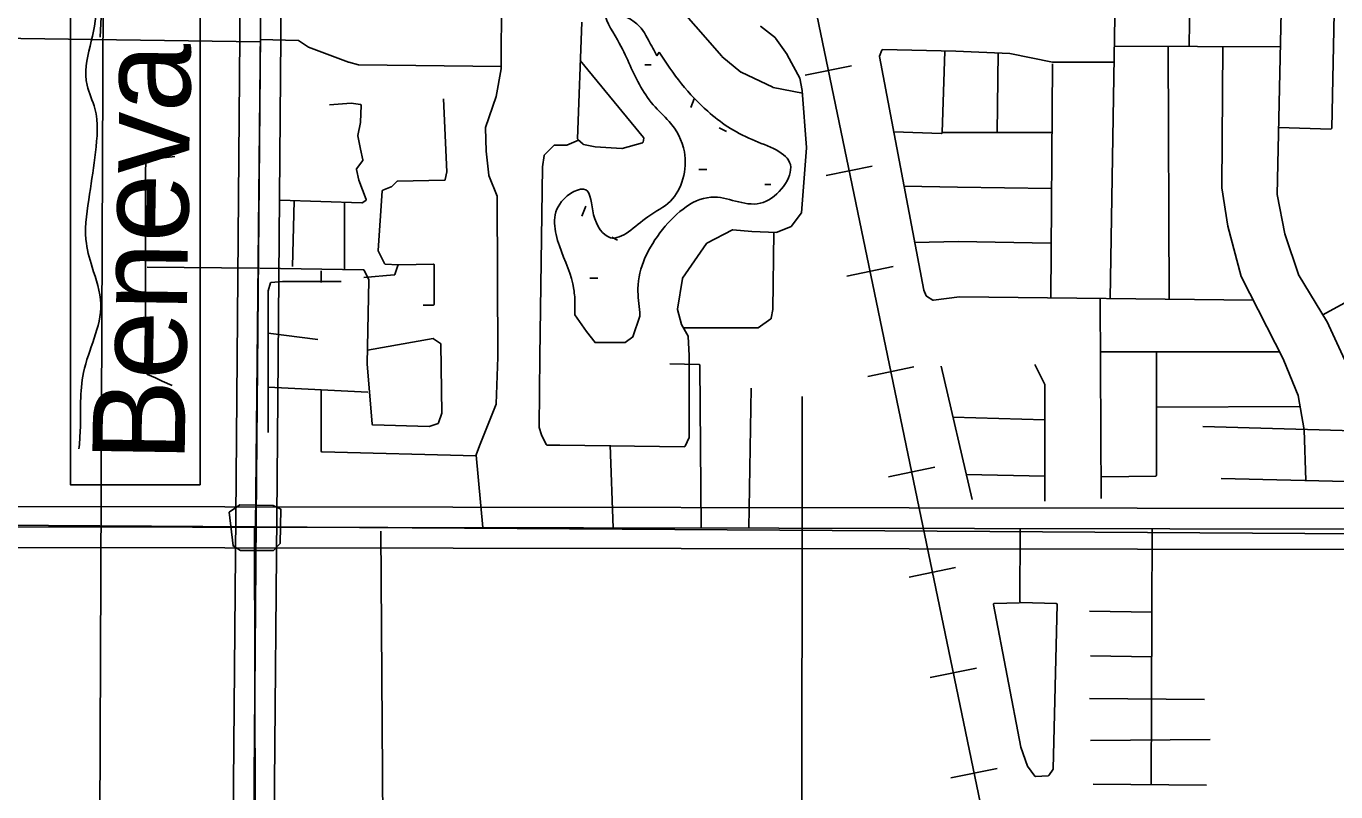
# Model space of a CAD drawing. Extents: x 408847 to 817539, y 923858 to 1151780.
# Drawn here: x 493482 to 499864, y 1076805 to 1080539 of the extents above; entities that cross this region are included whole.
import ezdxf

# ---------------------------------------------------------------- set-up
doc = ezdxf.new("R2010")
doc.units = 0
for name, color, linetype in [('County Roads Related Text', 7, 'Continuous'), ('County Route Divided Highway Outline and Fill', 7, 'Continuous'), ('County Routes Highway Center Lines', 7, 'Continuous'), ('Lakes and Ponds', 7, 'Continuous'), ('Level 12', 7, 'Continuous'), ('Level 7', 7, 'Continuous'), ('Level 8', 7, 'Continuous'), ('Local Roads Improved', 7, 'Continuous'), ('Local Roads Paved', 7, 'Continuous'), ('Masks for Road Features', 7, 'Continuous'), ('Masks for Text', 7, 'Continuous'), ('Narrow River Creek and Branch and Slough', 7, 'Continuous'), ('Quad Borders', 7, 'Continuous'), ('Railroads', 7, 'Continuous'), ('Section Lines', 7, 'Continuous'), ('Township  and Range lines', 7, 'Continuous')]:
    doc.layers.add(name, color=color, linetype=linetype)

msp = doc.modelspace()

# ---------------------------------------------------------------- linework, layer by layer
at = {"layer": 'County Route Divided Highway Outline and Fill'}
for p, q in [((494568, 1085769.8), (494505.3, 1078336)), ((494668, 1085769), (494605.3, 1078335.2)), ((494768, 1085768.2), (494705.3, 1078334.3)), ((494705.3, 1078334.3), (494768, 1085768.2)), ((494505.3, 1078336), (494302.9, 1054340.5)), ((494605.3, 1078335.2), (494402.6, 1054313.9)), ((494705.3, 1078334.3), (494502.5, 1054302.3)), ((494502.5, 1054302.3), (494705.3, 1078334.3))]:
    msp.add_line(p, q, dxfattribs=at)
at = {"layer": 'County Routes Highway Center Lines'}
for p, q in [((494605.3, 1078335.2), (494668, 1085769)), ((494402.6, 1054313.9), (494605.3, 1078335.2))]:
    msp.add_line(p, q, dxfattribs=at)
at = {"layer": 'Lakes and Ponds'}
msp.add_line((496567.6, 1080412.3), (496555.6, 1080394.3), dxfattribs=at)
msp.add_lwpolyline([(496155.4, 1079219.8), (496155.3, 1079131.6), (496212.2, 1079050.8), (496254.4, 1078995.7), (496401.2, 1078995.7), (496437.9, 1079023.2), (496472.7, 1079124.2), (496473.5, 1079143.5)], dxfattribs=at)
for points in [[(496555.6, 1080394.3), (496515.6, 1080470.4), (496445.5, 1080560.5), (496309.4, 1080602.5), (496363.4, 1080472.4), (496419.5, 1080360.3), (496537.3, 1080156.1), (496615.7, 1080074), (496689.8, 1079925.8), (496621.7, 1079685.6), (496511.6, 1079609.5), (496329.4, 1079507.4), (496247.3, 1079619.5), (496209.3, 1079741.6), (496091.2, 1079683.6), (496081.2, 1079467.4), (496151.2, 1079255.2), (496155.4, 1079219.8)], [(496473.5, 1079143.5), (496463.5, 1079259.2), (496583.7, 1079547.4), (496835.9, 1079705.6), (497074.2, 1079679.6), (497206.3, 1079863.8), (497020.1, 1079985.9), (496803.9, 1080124), (496675.8, 1080258.2), (496567.6, 1080412.3)]]:
    msp.add_spline(points, degree=3, dxfattribs=at)
at = {"layer": 'Level 12'}
for p, q in [((496497.8, 1080351.1), (496527.7, 1080351.1)), ((496859.7, 1080044.1), (496894.5, 1080025.4)), ((496760.2, 1079840.8), (496798.5, 1079840.8)), ((497081.2, 1079767.8), (497111, 1079767.8)), ((496190.9, 1079612.6), (496209.6, 1079661.1)), ((496229.9, 1079310.5), (496268.1, 1079310.5))]:
    msp.add_line(p, q, dxfattribs=at)
for points in [[(496721.3, 1080142.9), (496737.2, 1080184.4)], [(496336.8, 1079509.8), (496364.2, 1079495)]]:
    msp.add_lwpolyline(points, dxfattribs=at)
msp.add_spline([(493827.7, 1080893.9), (493803.6, 1080761.7), (493821.6, 1080635.6), (493778.8, 1080251.5), (493817.6, 1080137), (493819.6, 1079924.8), (493791.6, 1079720.6), (493773.6, 1079498.3), (493803.6, 1079364.2), (493845.7, 1079184), (493761.6, 1078849.6), (493745.6, 1078565.3), (493739.6, 1078477.2)], degree=3, dxfattribs=at)
at = {"layer": 'Level 7'}
for p, q in [((483896.7, 1078211.6), (513104.2, 1078166.3)), ((513104.1, 1078066.3), (483896.5, 1078111.6)), ((513103.9, 1077966.3), (483896.4, 1078011.6))]:
    msp.add_line(p, q, dxfattribs=at)
at = {"layer": 'Level 8'}
msp.add_line((494668, 1085769), (494605.3, 1078335.2), dxfattribs=at)
at = {"layer": 'Local Roads Improved'}
for p, q in [((496189.8, 1080558.8), (496169.5, 1079989.3)), ((496491, 1079997), (496181.6, 1080371.6)), ((496488.5, 1079973.6), (496491.9, 1079993.8)), ((496170.8, 1079986.1), (496197.2, 1079963.5)), ((496199, 1079962.7), (496254.9, 1079950.7)), ((496255.5, 1079950.6), (496385.3, 1079942.5)), ((496386.6, 1079942.6), (496485.6, 1079970.4))]:
    msp.add_line(p, q, dxfattribs=at)
for centre, start, end in [((496173.5, 1079989.2), 177.95554, 229.38551), ((496487.9, 1079994.4), 350.54201, 39.54656), ((496199.8, 1079966.6), 229.38551, 257.89977), ((496255.7, 1079954.6), 257.89977, 266.422), ((496385.5, 1079946.5), 266.422, 285.64918), ((496484.6, 1079974.2), 285.64918, 350.54201)]:
    msp.add_arc(centre, 4, start, end, dxfattribs=at)
at = {"layer": 'Local Roads Paved'}
for p, q in [((495801.7, 1081402.7), (495797.6, 1080331.1)), ((496190.9, 1081175.7), (496871.9, 1080392.3)), ((499158.1, 1081018.5), (499150, 1080440.3)), ((498794.5, 1081006.2), (498765.6, 1079211.4)), ((498765.6, 1079211.4), (498794.5, 1081006.2)), ((499607.4, 1081007.4), (499579, 1079719)), ((493859.5, 1080850.5), (493843, 1080486.1)), ((499844.6, 1080041.5), (499860.9, 1080863.1)), ((497133.2, 1080482.4), (497060.1, 1080539.2)), ((493103.5, 1080483.6), (494623.2, 1080463)), ((494623.3, 1080474.9), (494807.7, 1080469.8)), ((494809.8, 1080469.1), (494857.5, 1080437.3)), ((494858.3, 1080436.9), (495053.8, 1080363.5)), ((497190.7, 1080400.5), (497134, 1080481.5)), ((498785.4, 1080442.2), (499594.8, 1080438)), ((499047.8, 1080440.8), (499051.9, 1079208.1)), ((499313.4, 1080439.5), (499309.3, 1079751.6)), ((496872.4, 1080391.9), (496965.7, 1080314.7)), ((497251.8, 1080286.3), (497190.9, 1080400)), ((497640.5, 1080391), (497856.7, 1079252)), ((497651.5, 1080422.1), (497640.7, 1080393.1)), ((498012.1, 1080416.6), (497655.4, 1080424.7)), ((497946.8, 1080020), (497959.4, 1080417.8)), ((497959.4, 1080417.8), (497946.8, 1080020)), ((498275.3, 1080405.3), (498012.1, 1080416.6)), ((498214.1, 1080021), (498218.4, 1080409.4)), ((498483.6, 1080364.5), (498275.9, 1080405.3)), ((495054.2, 1080363.4), (495102.5, 1080351.3)), ((495103.5, 1080351.2), (495797.6, 1080343)), ((495797.5, 1080330.4), (495773.1, 1080196.2)), ((496966.6, 1080314.2), (497120.9, 1080241.1)), ((498475.7, 1079214.7), (498484, 1080356.3)), ((498784.2, 1080364.5), (498484.4, 1080364.5)), ((497264.3, 1080224.7), (497252.2, 1080285.2)), ((495532, 1079829.4), (495515.7, 1080184.6)), ((495773, 1080195.6), (495720.2, 1080045.3)), ((497121.9, 1080240.7), (497265.2, 1080213)), ((497284.8, 1079946.8), (497264.4, 1080224.2)), ((495065.7, 1080164.1), (494960, 1080156)), ((495111.8, 1080156.5), (495066.7, 1080164.1)), ((495111.2, 1080070.4), (495115.1, 1080152.4)), ((495099.1, 1080005.4), (495111.1, 1080069.8)), ((495111.2, 1079939.4), (495099.1, 1080004)), ((495720, 1080043.9), (495724, 1079930.3)), ((497710.1, 1080024.5), (497942.7, 1080016.2)), ((497942.7, 1080016.2), (497710.1, 1080024.5)), ((497946.9, 1080021), (498481.5, 1080021)), ((499587.1, 1080045.6), (499840.5, 1080037.6)), ((495123, 1079887.9), (495111.2, 1079939.2)), ((495724.1, 1079930), (495736.2, 1079812.2)), ((496053.8, 1079957.6), (496006.9, 1079910.7)), ((496053.8, 1079957.6), (496006.9, 1079910.7)), ((496115.5, 1079958.8), (496056.6, 1079958.8)), ((496115.5, 1079958.8), (496056.6, 1079958.8)), ((496174.5, 1079983), (496117, 1079959.1)), ((496174.5, 1079983), (496117, 1079959.1)), ((497260.4, 1079628.8), (497284.8, 1079946.2)), ((494067.4, 1079883.6), (494063.6, 1079842)), ((494206.6, 1079903.2), (494070.9, 1079887.2)), ((495091.8, 1079842.7), (495122.4, 1079884.7)), ((496005.8, 1079908.4), (495997.8, 1079852.8)), ((496005.8, 1079908.4), (495997.8, 1079852.8)), ((494063.6, 1079841.7), (494063.6, 1078901.9)), ((495102.9, 1079788.3), (495091.2, 1079839.4)), ((495524.5, 1079791.2), (495531.9, 1079828.5)), ((495736.5, 1079811.1), (495776.9, 1079710.1)), ((495997.8, 1079852.2), (495985.5, 1078928.7)), ((495997.8, 1079852.2), (495985.5, 1078928.7)), ((495138.6, 1079693.1), (495103.1, 1079787.8)), ((495197, 1079445.8), (495217.2, 1079736.4)), ((495219.8, 1079739.9), (495261.5, 1079755.1)), ((495263, 1079756), (495289.8, 1079782.8)), ((495292.6, 1079784), (495520.6, 1079788)), ((497760.5, 1079758.7), (498020.2, 1079754.4)), ((498020.2, 1079754.4), (498479.6, 1079747)), ((499309.3, 1079751), (499337.9, 1079563.5)), ((494718.9, 1079690), (495118.2, 1079677.7)), ((494780.2, 1079367), (494788.7, 1079687.8)), ((495033.5, 1079354.8), (495033.2, 1079680.3)), ((495120.4, 1079678.3), (495136.9, 1079688.2)), ((495777.2, 1079708.7), (495781.2, 1078924.6)), ((499579, 1079718.2), (499615.7, 1079526.8)), ((497211.9, 1079563.2), (497259.6, 1079626.8)), ((496799.5, 1079481), (496924.2, 1079545.4)), ((496926.4, 1079545.8), (497019.1, 1079537.8)), ((497142.6, 1079534), (497210.2, 1079561.9)), ((499337.9, 1079563.1), (499403.2, 1079318.4)), ((496680.6, 1079309.6), (496798, 1079479.7)), ((497019.3, 1079537.8), (497140.9, 1079533.7)), ((497121.4, 1079157.9), (497125.7, 1079534.2)), ((497812.6, 1079484.3), (498024.3, 1079488.7)), ((498024.3, 1079488.7), (498475.8, 1079481.5)), ((499615.8, 1079526.2), (499685, 1079322.5)), ((495228.6, 1079381.4), (495197.5, 1079443.7)), ((494071.8, 1079363.6), (494613.9, 1079359)), ((494620.9, 1079358.9), (495125.1, 1079350.7)), ((495295, 1079375.2), (495232, 1079379.2)), ((495279.5, 1079328.7), (495294.1, 1079372.5)), ((495297.8, 1079375.3), (495466.6, 1079379.2)), ((495470.7, 1079375.2), (495470.7, 1079183)), ((499801.8, 1079131.2), (500263.3, 1079387.3)), ((494661.9, 1079249.1), (494673.2, 1079286.7)), ((494676.7, 1079289.6), (494731.1, 1079293.4)), ((494731.3, 1079293.5), (495017.2, 1079293.5)), ((494919.1, 1079289.4), (494919.1, 1079346.6)), ((495127.5, 1079313.9), (495276.1, 1079325.9)), ((495128.6, 1079348.5), (495151.6, 1079302.5)), ((495152, 1079300.6), (495143.9, 1078893.1)), ((496655.7, 1079158.5), (496680, 1079308)), ((499403.5, 1079317.6), (499611.6, 1078909.4)), ((499685.4, 1079321.7), (499819.9, 1079101.6)), ((494661.7, 1078557.7), (494661.7, 1079247.9)), ((497857, 1079251.2), (497868.6, 1079224.2)), ((497870.1, 1079222.3), (497900.5, 1079203.3)), ((495466.7, 1079179), (495417.6, 1079179)), ((497903.2, 1079202.8), (498030.4, 1079219.9)), ((498030.4, 1079219.9), (499461.7, 1079203.3)), ((498716.9, 1079211.7), (498720.9, 1078234.8)), ((496675.9, 1079084.5), (496655.8, 1079156.8)), ((497048.9, 1079068.4), (497111.8, 1079111.7)), ((497113.5, 1079114.3), (497121.3, 1079157.3)), ((499820.1, 1079101.2), (499917.9, 1078889.1)), ((494661.7, 1079042.1), (494902.8, 1079011.4)), ((496708.2, 1079027.6), (496676.3, 1079083.6)), ((496685.4, 1079067.7), (497046.6, 1079067.7)), ((495465.1, 1079015.2), (495145.2, 1078959.6)), ((495501.7, 1078992.1), (495468, 1079014.6)), ((495507.5, 1078652.4), (495503.4, 1078988.9)), ((496712.8, 1078933.7), (496708.8, 1079025.8)), ((495781.2, 1078924.6), (495773.1, 1078697.3)), ((495985.5, 1078928.7), (495981.4, 1078582.9)), ((496712.8, 1078534), (496712.8, 1078933.7)), ((498717.9, 1078950.1), (499590.8, 1078950.1)), ((498990.6, 1078946), (498990.6, 1078349.1)), ((499611.7, 1078909.1), (499680.9, 1078738)), ((494063.6, 1078901.4), (494071.5, 1078842.7)), ((494073.9, 1078839.5), (494112.5, 1078824.1)), ((495143.9, 1078892.7), (495168.1, 1078598)), ((496618.8, 1078892.9), (496762, 1078888.9)), ((496765.9, 1078884.9), (496771, 1078091.6)), ((497940.6, 1078880.6), (498091.7, 1078230.7)), ((498398.2, 1078888.8), (498446.8, 1078791.5)), ((494112.8, 1078823.9), (494145.2, 1078807.7)), ((494145.4, 1078807.6), (494194.3, 1078787.2)), ((495147.9, 1078753.9), (494661.7, 1078779)), ((498447.2, 1078789.8), (498447.2, 1078222.5)), ((494919.1, 1078762.1), (494919.1, 1078467.5)), ((497015.1, 1078774.3), (497004.6, 1078091.3)), ((497264.4, 1078733.4), (497264.4, 1078255.2)), ((499681.2, 1078737.1), (499709.7, 1078570.2)), ((495491.8, 1078604.5), (495507.3, 1078651.1)), ((495772.8, 1078696), (495691.4, 1078492.3)), ((499690.2, 1078684.4), (498990.6, 1078680.2)), ((495171.9, 1078594.4), (495445.4, 1078586.3)), ((495446.9, 1078586.5), (495489.3, 1078602)), ((498447.2, 1078618.7), (497998.4, 1078631.9)), ((495981.7, 1078581.6), (495993.6, 1078545.7)), ((495993.8, 1078545.2), (496017.1, 1078498.6)), ((496693.4, 1078490.6), (496712.4, 1078532.4)), ((499709.7, 1078569.7), (499718.4, 1078323)), ((494923, 1078463.6), (495675, 1078443.2)), ((495691.3, 1078492.2), (495675.3, 1078448.1)), ((496020.7, 1078496.4), (496083.6, 1078496.4)), ((496083.6, 1078496.4), (496689.8, 1078488.2)), ((496328.7, 1078496.4), (496342.2, 1078092.3)), ((495675.1, 1078446.4), (495707.2, 1078093.3)), ((498063.3, 1078353.1), (498447.2, 1078344.8)), ((498986.7, 1078345.1), (498725, 1078341.1)), ((499305.2, 1078332.9), (499985.1, 1078316.8)), ((497259.1, 1075172.4), (497264.4, 1078255.2)), ((495210.4, 1078075.4), (495219.7, 1076637.8)), ((498325.7, 1078085.4), (498325.2, 1077731.5)), ((498969.6, 1078088.2), (498964.8, 1076839.5)), ((498329.8, 1077023), (498196.3, 1077718.3)), ((498200.1, 1077723.1), (498323.7, 1077726.4)), ((498329.1, 1077727.5), (498502, 1077723)), ((498505.9, 1077719), (498487.5, 1076917.3)), ((498663.6, 1077685.8), (498968, 1077680.9)), ((498668.2, 1077467.9), (498967.2, 1077462.9)), ((498663.6, 1077259.2), (499224.4, 1077254.6)), ((498668.2, 1077055.2), (499252.2, 1077059.8)), ((498362.1, 1076930.5), (498329.9, 1077022.4)), ((498398.1, 1076880.7), (498362.6, 1076929.5)), ((498462.4, 1076883.5), (498401.6, 1076879.1)), ((498486.7, 1076915), (498465.4, 1076885.1)), ((498682.1, 1076841.9), (499233.7, 1076837.2))]:
    msp.add_line(p, q, dxfattribs=at)
for centre, start, end in [((497062.6, 1080542.4), 230.61759, 232.11208), ((494807.6, 1080465.8), 56.29761, 88.40812), ((494859.7, 1080440.6), 236.29761, 249.43517), ((497130.7, 1080479.2), 34.97948, 52.11207), ((496874.9, 1080395), 221.00325, 230.42722), ((497187.4, 1080398.2), 28.16748, 34.97948), ((497644.4, 1080391.7), 159.45273, 190.75109), ((497655.3, 1080420.7), 88.69744, 159.45273), ((498275.1, 1080401.3), 78.90124, 87.55005), ((495055.2, 1080367.3), 249.43517, 255.95747), ((495103.5, 1080355.2), 255.95747, 269.32565), ((495793.6, 1080331.1), 349.69985, 359.78225), ((496968.3, 1080317.8), 230.42722, 244.64349), ((498484.4, 1080368.5), 258.90123, 270), ((497248.3, 1080284.4), 11.3048, 28.16748), ((495769.2, 1080196.9), 340.64936, 349.69985), ((497122.6, 1080244.7), 244.64349, 259.04095), ((497260.4, 1080223.9), 4.2034, 11.3048), ((495066.1, 1080160.1), 80.53335, 94.40075), ((495111.1, 1080152.6), 357.27496, 80.53335), ((495107.2, 1080070.6), 349.38518, 357.27496), ((495103, 1080004.7), 169.38518, 190.61482), ((495724, 1080044), 160.64936, 182.04446), ((497942.8, 1080020.2), 267.95364, 358.1921), ((497942.8, 1080020.2), 267.95364, 358.1921), ((499840.6, 1080041.6), 268.18085, 358.86611), ((495115.1, 1079940.1), 190.61482, 192.98877), ((495728, 1079930.5), 182.04446, 185.90341), ((496056.6, 1079954.8), 90, 135.01335), ((496056.6, 1079954.8), 90, 135.01335), ((496115.5, 1079962.8), 270, 292.62935), ((496115.5, 1079962.8), 270, 292.62935), ((497280.8, 1079946.5), 355.60334, 4.20341), ((494071.4, 1079883.2), 96.71294, 174.80798), ((495119.1, 1079887), 323.98533, 12.98877), ((496009.7, 1079907.8), 135.01335, 171.87364), ((496009.7, 1079907.8), 135.01335, 171.87364), ((494067.6, 1079841.7), 174.80798, 180), ((495095.1, 1079840.3), 143.98533, 192.98877), ((495528, 1079829.2), 348.6952, 2.63121), ((495740.2, 1079812.6), 185.90341, 201.7922), ((496001.8, 1079852.2), 171.87364, 179.23984), ((496001.8, 1079852.2), 171.87364, 179.23984), ((495106.8, 1079789.2), 192.98877, 200.54727), ((495221.2, 1079736.1), 109.99168, 176.02935), ((495260.1, 1079758.8), 289.99168, 315.01335), ((495292.6, 1079780), 91.00555, 135.01335), ((495520.5, 1079792), 271.00555, 348.6952), ((499313.3, 1079751.6), 179.65708, 188.64857), ((495118.3, 1079681.7), 268.24578, 300.97554), ((495134.9, 1079691.7), 300.97554, 20.54727), ((495773.2, 1079708.7), 0.29827, 21.7922), ((499583, 1079718.9), 178.73628, 190.83537), ((497256.4, 1079629.2), 323.14292, 355.60334), ((496926.1, 1079541.8), 85.02796, 117.31046), ((497208.7, 1079565.6), 292.38954, 323.14292), ((499341.8, 1079564.1), 188.64857, 194.92477), ((496801.3, 1079477.4), 117.31045, 145.38833), ((497019.5, 1079541.8), 265.02795, 268.08996), ((497141.1, 1079537.7), 268.08996, 292.38954), ((499619.6, 1079527.5), 190.83537, 198.7699), ((495201, 1079445.5), 176.02935, 206.55437), ((495125, 1079346.7), 26.55437, 89.07552), ((495232.2, 1079383.1), 206.55437, 266.422), ((495297.9, 1079371.3), 91.33284, 161.57306), ((495466.7, 1079375.2), 0, 91.33284), ((494677, 1079285.6), 94.08751, 163.3081), ((494731.3, 1079289.5), 90, 94.08751), ((495148, 1079300.7), 358.85477, 26.55437), ((495275.7, 1079329.9), 274.63761, 341.57306), ((496683.9, 1079307.3), 145.38833, 170.79319), ((499407, 1079319.4), 194.92477, 207.01078), ((499688.8, 1079323.8), 198.7699, 211.41769), ((494665.7, 1079247.9), 163.3081, 180), ((497860.7, 1079252.8), 190.75109, 203.18892), ((497872.3, 1079225.7), 203.18892, 237.98261), ((495466.7, 1079183), 270, 0), ((496659.7, 1079157.8), 170.79319, 195.51723), ((497902.7, 1079206.7), 237.98261, 277.67353), ((497109.6, 1079115), 304.52099, 349.69985), ((497117.4, 1079158), 349.69985, 359.34176), ((499816.5, 1079099.5), 24.76498, 31.41769), ((496679.7, 1079085.6), 195.51722, 209.73338), ((497046.6, 1079071.7), 270, 304.52099), ((495465.7, 1079011.3), 56.29761, 99.87032), ((495499.4, 1078988.8), 0.68996, 56.29761), ((496704.8, 1079025.7), 2.51403, 29.73338), ((499608, 1078907.6), 22.02694, 27.01078), ((494067.6, 1078901.9), 180, 187.59115), ((494075.4, 1078843.2), 187.59115, 248.18938), ((495147.9, 1078893), 178.85477, 184.6965), ((496761.9, 1078884.9), 0.36246, 88.40812), ((494111, 1078820.4), 63.42427, 68.18938), ((494147, 1078811.3), 243.42427, 247.37065), ((498443.2, 1078789.8), 0, 26.55437), ((499677.2, 1078736.5), 9.68436, 22.02694), ((495503.5, 1078652.3), 341.57306, 0.68996), ((495769.1, 1078697.5), 338.2078, 357.94694), ((495172.1, 1078598.4), 184.6965, 268.31453), ((495445.6, 1078590.3), 268.31453, 289.99168), ((495488, 1078605.7), 289.99168, 341.57306), ((495985.4, 1078582.8), 179.32441, 198.42694), ((495997.4, 1078546.9), 198.42694, 206.55437), ((496708.8, 1078534), 335.5661, 360), ((499705.7, 1078569.6), 2.00862, 9.68436), ((494923.1, 1078467.5), 180, 268.45112), ((495695.1, 1078490.8), 158.2078, 160.02547), ((496020.7, 1078500.4), 206.55437, 270), ((496083.6, 1078492.4), 89.23062, 90), ((496689.8, 1078492.2), 269.23062, 335.5661), ((495679.1, 1078446.8), 160.02547, 185.19202), ((498986.6, 1078349.1), 270.88181, 0), ((498200.2, 1077719.1), 91.5561, 190.86651), ((498329.2, 1077731.5), 179.93015, 268.53052), ((498501.9, 1077719), 358.6837, 88.53052), ((498333.7, 1077023.8), 190.86651, 199.28173), ((498365.9, 1076931.8), 199.28173, 216.01468), ((498401.3, 1076883.1), 216.01468, 274.08751), ((498462.1, 1076887.4), 274.08751, 324.47494), ((498483.5, 1076917.4), 324.47494, 358.6837)]:
    msp.add_arc(centre, 4, start, end, dxfattribs=at)
at = {"layer": 'Masks for Road Features'}
msp.add_lwpolyline([(494472.1, 1078168.4), (494523.2, 1078204.3), (494686.4, 1078202), (494723, 1078183.7), (494720.7, 1078016.6), (494687.1, 1077982.2), (494526.2, 1077982.2), (494490.4, 1078004.4)], close=True, dxfattribs=at)
at = {"layer": 'Masks for Text'}
msp.add_lwpolyline([(494330.7, 1078301.5), (493698.3, 1078301.5), (493698.3, 1081095.7), (494330.7, 1081095.7)], close=True, dxfattribs=at)
at = {"layer": 'Narrow River Creek and Branch and Slough'}
msp.add_line((500305.4, 1078554.5), (499216.3, 1078586.5), dxfattribs=at)
msp.add_spline([(486723.1, 1073260.8), (486698, 1073347), (486670.2, 1073486.2), (486689.7, 1073674.8), (486669.6, 1074009.1), (486603.6, 1074303.3), (486709.7, 1074593.5), (486871.8, 1074961.8), (486885.8, 1075338.1), (486949.9, 1075628.4), (487035.9, 1075956.6), (487058, 1076212.8), (487150, 1076403), (487350.2, 1076681.2), (487398.2, 1076867.4), (487294.2, 1077033.5), (487196.1, 1077165.6), (487122, 1077311.7), (487192.1, 1077405.8), (487388.2, 1077596), (487524.3, 1077836.1), (487656.4, 1078076.3), (487860.6, 1078456.6), (488068.8, 1078718.9), (488232.9, 1078965.1), (488375, 1079183.2), (488625.2, 1079495.5), (488883.4, 1079763.7), (489079.6, 1079893.8), (489345.8, 1080045.9), (489523.9, 1080238.1), (489860.2, 1080616.4), (490032.3, 1080894.6), (490402.6, 1081290.9), (490574.8, 1081607.2), (490716.9, 1081963.5), (490869, 1082353.8), (490951.1, 1082668), (491067.2, 1083110.4), (491177.3, 1083486.7), (491319.4, 1083841), (491513.5, 1084137.2), (491679.7, 1084427.5), (491833.8, 1084707.7), (492074, 1084963.9), (492312.2, 1085234.1), (492384.2, 1085326.2), (492382.2, 1085474.3), (492258.1, 1086028.7), (492144, 1086283), (492056, 1086559.2), (492104, 1086869.4), (492230.1, 1086981.5), (492606.4, 1087235.7), (492778.6, 1087439.9), (492914.7, 1087652.1), (493152.9, 1087926.3), (493375, 1088010.3), (493629.2, 1087996.3), (493805.4, 1087974.3), (493907.5, 1087984.3)], degree=3, dxfattribs=at)
at = {"layer": 'Quad Borders'}
msp.add_line((493776.8, 1060493), (493958.9, 1105932.5), dxfattribs=at)
msp.add_line((493776.8, 1060493), (493958.9, 1105932.5), dxfattribs=at)
at = {"layer": 'Railroads'}
for p, q in [((501512.6, 1060426.3), (495655.5, 1088705.6)), ((497279, 1080299.7), (497504.3, 1080346.4)), ((497380.5, 1079810.1), (497605.7, 1079856.8)), ((497481.9, 1079320.5), (497707.1, 1079367.1)), ((497583.3, 1078830.9), (497808.5, 1078877.5)), ((497684.7, 1078341.3), (497909.9, 1078387.9)), ((497786.1, 1077851.7), (498011.3, 1077898.3)), ((497887.5, 1077362.1), (498112.7, 1077408.7)), ((497988.9, 1076872.4), (498214.1, 1076919.1))]:
    msp.add_line(p, q, dxfattribs=at)
msp.add_lwpolyline([(510079.2, 1019797.2), (501500.3, 1060485.3), (501512.6, 1060426.3), (495655.5, 1088705.6), (495655.5, 1088705.6), (495297.5, 1089286.4), (494680.1, 1089502.7), (494680.1, 1089502.7), (486588.8, 1089533.8), (486588.8, 1089533.8), (485948.3, 1089769.1), (485607.8, 1090360.4), (485592.6, 1090534.9), (485592.6, 1090534.9), (485598.8, 1095821.6), (485577.9, 1096140.9), (484280, 1105896.4), (484264.6, 1106103.9), (484317, 1113718.1)], dxfattribs=at)
at = {"layer": 'Section Lines'}
for p, q in [((494600.2, 1078099), (494661.4, 1084143.6)), ((494595.2, 1078097.6), (494603.7, 1072756.6))]:
    msp.add_line(p, q, dxfattribs=at)
at = {"layer": 'Township  and Range lines'}
for p, q in [((489297.5, 1078132), (494595.2, 1078097.6)), ((494595.2, 1078097.6), (499969.8, 1078062.7))]:
    msp.add_line(p, q, dxfattribs=at)

# ---------------------------------------------------------------- texts
at = {"layer": 'County Roads Related Text'}
msp.add_text('Beneva', height=450, rotation=89.12117, dxfattribs=at).set_placement((494254.1, 1078411.5))

doc.saveas('drawing.dxf')
